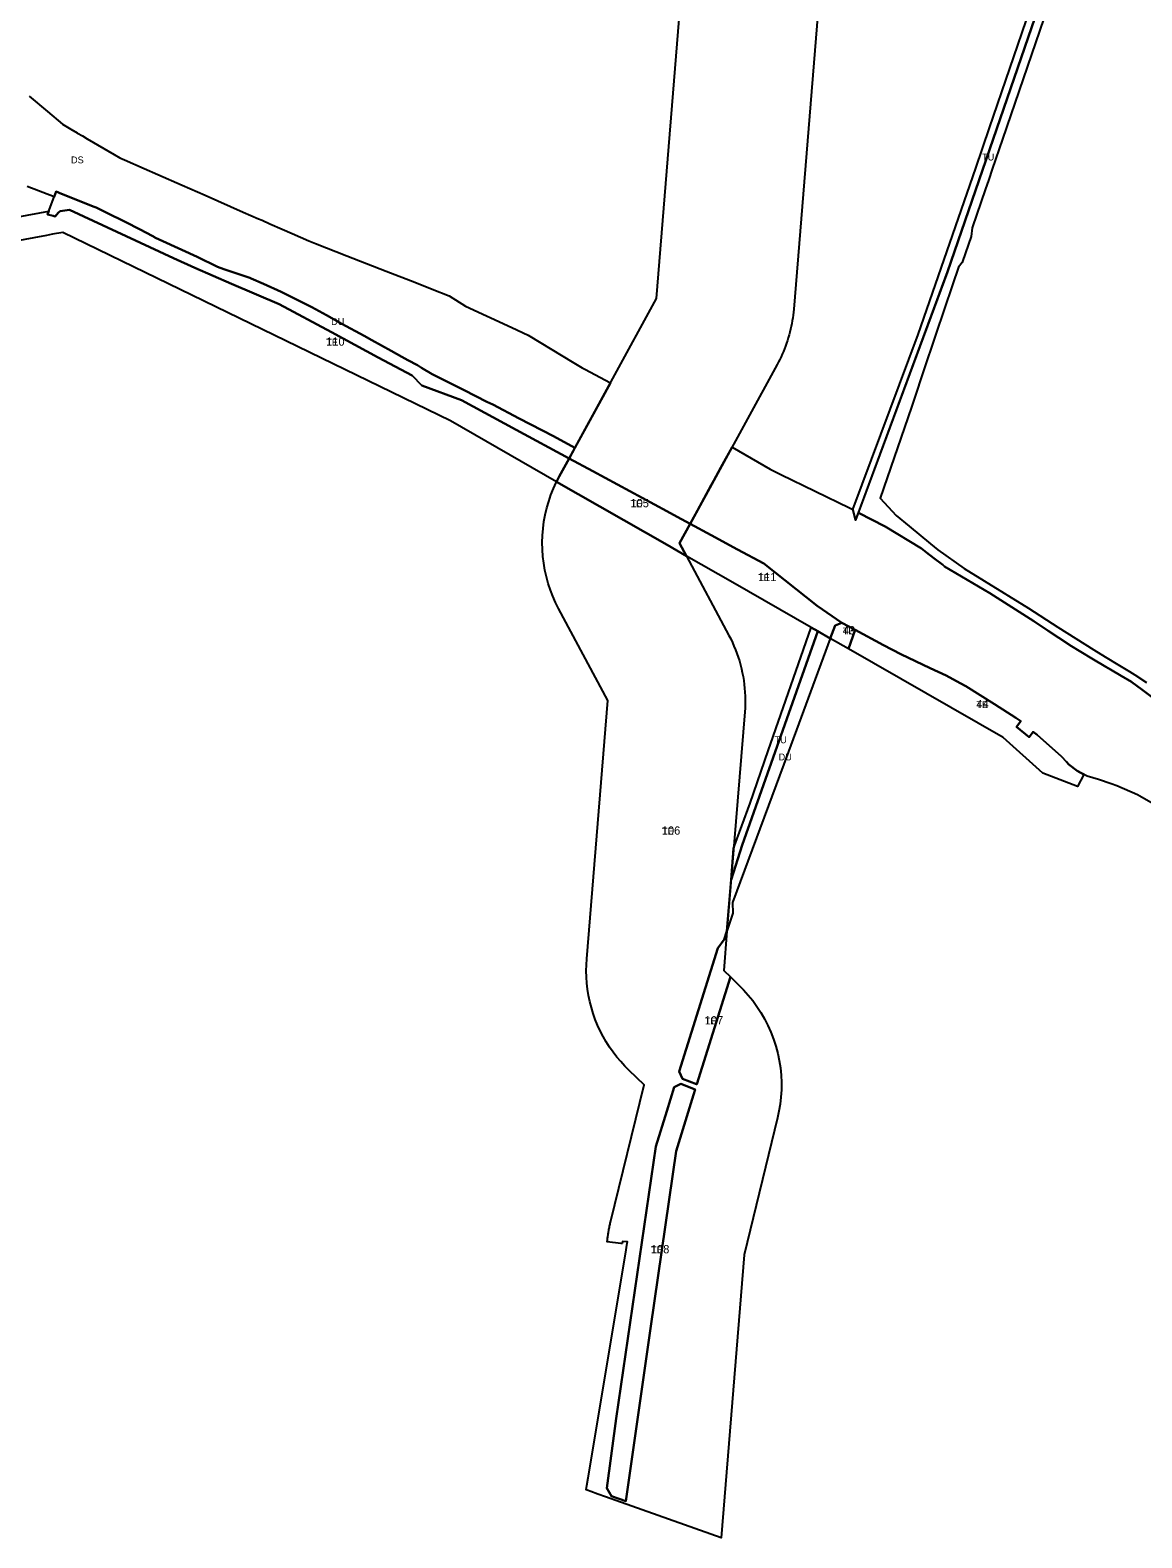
# Model space of a CAD drawing. Extents: x -545758 to -541641, y -1153152 to -1149975.
# Drawn here: x -545298 to -544489, y -1153152 to -1152056 of the extents above; entities that cross this region are included whole.
import ezdxf

# ---------------------------------------------------------------- set-up
doc = ezdxf.new("R2010")
doc.units = 0
for name, color, linetype in [('90310013', 7, 'Continuous'), ('90320013', 7, 'Continuous'), ('90380013', 7, 'Continuous'), ('90400023', 7, 'Continuous'), ('ID_navrh', 7, 'Continuous')]:
    doc.layers.add(name, color=color, linetype=linetype)

msp = doc.modelspace()

# ---------------------------------------------------------------- linework, layer by layer
at = {"layer": '90310013'}
for points in [[(-544481.23, -1152541), (-544489.11, -1152535.08), (-544496.36, -1152529.63), (-544496.46, -1152529.57), (-544504.15, -1152525.05), (-544511.83, -1152520.54), (-544515.2, -1152518.56), (-544525.39, -1152512.41), (-544541.43, -1152502.75), (-544541.58, -1152502.66), (-544557.13, -1152492.31), (-544567.56, -1152485.36), (-544599.6, -1152464.94), (-544632.56, -1152445.54), (-544633.87, -1152444.53), (-544640.28, -1152439.57), (-544645.63, -1152435.46), (-544649.29, -1152432.65), (-544675.73, -1152416.43), (-544695.241, -1152406.541), (-544630.44, -1152231.35), (-544571.74, -1152060.98), (-544513.04, -1151890.62)], [(-544560.42, -1152047.27), (-544590.33, -1152134.84), (-544597.88, -1152156.75), (-544600.43, -1152164.15), (-544603.03, -1152171.72), (-544606, -1152180.35), (-544612.56, -1152199.38), (-544613.15, -1152205.7), (-544617.23, -1152217.55), (-544619.66, -1152224.61), (-544622.37, -1152227.91), (-544626.78, -1152240.84), (-544638.99, -1152276.62), (-544641.43, -1152283.98), (-544645.92, -1152297.5), (-544656.61, -1152329.75), (-544679.3, -1152395.86), (-544667.8, -1152408.57), (-544658.35, -1152416.34), (-544642.8, -1152429.13), (-544637.45, -1152433.53), (-544618.29, -1152447.13), (-544603.68, -1152456.06), (-544571.54, -1152475.88), (-544550.16, -1152489.69), (-544523.97, -1152506.3), (-544515.72, -1152511.34), (-544506.5, -1152516.81), (-544498.11, -1152522), (-544494.22, -1152524.49), (-544485.69, -1152529.96)]]:
    msp.add_lwpolyline(points, dxfattribs=at)
for points in [[(-544901.361, -1152359.376), (-544905.561, -1152367.062), (-544944.14, -1152346.23), (-544983.88, -1152324.78), (-545012.67, -1152314.02), (-545019.73, -1152306.85), (-545044.41, -1152293.58), (-545078.51, -1152275.23), (-545116.45, -1152254.83), (-545151.09, -1152240.06), (-545177.97, -1152228.5), (-545193.36, -1152221.36), (-545269.04, -1152186.2), (-545275.73, -1152187.34), (-545277.02, -1152188.25), (-545278.59, -1152189.93), (-545279.36, -1152191.17), (-545281, -1152190.74), (-545284.96, -1152189.71), (-545280.21, -1152176.92), (-545278.79, -1152173), (-545274.74, -1152174.61), (-545251, -1152184.04), (-545249.66, -1152184.69), (-545241.98, -1152188.44), (-545228.61, -1152194.99), (-545227.97, -1152195.32), (-545218.21, -1152200.42), (-545208.46, -1152205.51), (-545206.49, -1152206.54), (-545201.09, -1152209.03), (-545176.24, -1152220.48), (-545161.43, -1152227.73), (-545156.68, -1152229.35), (-545145.25, -1152233.25), (-545137.75, -1152235.82), (-545136.81, -1152236.24), (-545127.98, -1152240.19), (-545115.02, -1152246), (-545092.74, -1152257.13), (-545082.1, -1152262.99), (-545070.9, -1152269.17), (-545054.69, -1152277.97), (-545049, -1152281.07), (-545035.06, -1152288.88), (-545027.26, -1152293.25), (-545023.01, -1152295.52), (-545015.99, -1152299.27), (-545012.93, -1152301.13), (-545005.28, -1152305.8), (-544982.08, -1152317.42), (-544965.36, -1152325.79), (-544961.14, -1152327.91), (-544941.85, -1152337.92), (-544916.99, -1152350.83)], [(-544790.854, -1152710.719), (-544787.811, -1152673.363), (-544779.71, -1152648.34), (-544724.668, -1152492.775), (-544715.712, -1152497.902), (-544749.46, -1152589.25), (-544786.7, -1152690.05), (-544786.64, -1152697.75)]]:
    msp.add_lwpolyline(points, close=True, dxfattribs=at)
at = {"layer": '90320013'}
for points in [[(-545298.3, -1152103.62), (-545285.05, -1152114.86), (-545274.15, -1152124.11), (-545267.99, -1152127.69), (-545263.39, -1152130.37), (-545263.11, -1152130.53), (-545259.63, -1152132.56), (-545259.58, -1152132.59), (-545256.06, -1152134.64), (-545236.53, -1152146.01), (-545232.45, -1152148.39), (-545229.05, -1152149.89), (-545228.91, -1152149.95), (-545214.72, -1152156.19), (-545204.71, -1152160.59), (-545196.9, -1152164.02), (-545194.72, -1152164.98), (-545187.16, -1152168.31), (-545170.34, -1152175.71), (-545142.62, -1152187.9), (-545131.55, -1152192.77), (-545128.96, -1152193.9), (-545123.33, -1152196.38), (-545114.46, -1152200.28), (-545107.13, -1152203.5), (-545094.87, -1152208.89), (-545089.98, -1152210.8), (-545067.38, -1152219.63), (-545038.6, -1152230.87), (-545017.89, -1152238.96), (-545005.27, -1152243.89), (-544992.95, -1152248.71), (-544981.08, -1152256.44), (-544947.32, -1152271.94), (-544935.3, -1152277.46), (-544902.29, -1152297.51), (-544896.18, -1152301.23), (-544894.29, -1152302.21), (-544875.471, -1152311.992), (-544901.361, -1152359.376), (-544916.99, -1152350.83), (-544941.85, -1152337.92), (-544961.14, -1152327.91), (-544965.36, -1152325.79), (-544982.08, -1152317.42), (-545005.28, -1152305.8), (-545012.93, -1152301.13), (-545015.99, -1152299.27), (-545023.01, -1152295.52), (-545027.26, -1152293.25), (-545035.06, -1152288.88), (-545049, -1152281.07), (-545054.69, -1152277.97), (-545070.9, -1152269.17), (-545082.1, -1152262.99), (-545092.74, -1152257.13), (-545115.02, -1152246), (-545127.98, -1152240.19), (-545136.81, -1152236.24), (-545137.75, -1152235.82), (-545145.25, -1152233.25), (-545156.68, -1152229.35), (-545161.43, -1152227.73), (-545176.24, -1152220.48), (-545201.09, -1152209.03), (-545206.49, -1152206.54), (-545208.46, -1152205.51), (-545218.21, -1152200.42), (-545227.97, -1152195.32), (-545228.61, -1152194.99), (-545241.98, -1152188.44), (-545249.66, -1152184.69), (-545251, -1152184.04), (-545274.74, -1152174.61), (-545278.79, -1152173), (-545280.21, -1152176.92), (-545299.89, -1152169.25)], [(-544475.81, -1152621.01), (-544490.57, -1152612.64), (-544492.33, -1152611.64), (-544507.3, -1152605.14), (-544511.43, -1152603.7), (-544520.47, -1152600.54), (-544528.77, -1152598.15), (-544536.19, -1152594.18), (-544542.2, -1152589.58), (-544543.88, -1152587.78), (-544547.55, -1152583.86), (-544565.31, -1152568.13), (-544568.11, -1152565.86), (-544570.95, -1152569.65), (-544580.27, -1152562.1), (-544577.06, -1152558.13), (-544580.79, -1152555.56), (-544596.19, -1152545.83), (-544617.01, -1152532.67), (-544621.12, -1152530.46), (-544631.29, -1152525.01), (-544642.93, -1152519.54), (-544664.42, -1152509.45), (-544676.91, -1152502.94), (-544697.46, -1152491.78), (-544707.28, -1152486.57), (-544725.21, -1152474.29), (-544764.06, -1152443.46), (-544783.135, -1152433.165), (-544783.135, -1152433.165), (-544802.23, -1152422.86), (-544817.569, -1152414.576), (-544817.569, -1152414.576), (-544813.735, -1152407.56), (-544807.394, -1152395.955), (-544802.253, -1152386.546), (-544800.315, -1152383), (-544795.19, -1152373.62), (-544787.104, -1152358.82), (-544759.32, -1152374.84), (-544751.588, -1152378.627), (-544751.588, -1152378.627), (-544701.77, -1152403.03), (-544699.22, -1152404.28), (-544697.22, -1152411.89), (-544695.241, -1152406.541), (-544695.241, -1152406.541), (-544675.73, -1152416.43), (-544649.29, -1152432.65), (-544645.63, -1152435.46), (-544640.28, -1152439.57), (-544633.87, -1152444.53), (-544632.56, -1152445.54), (-544599.6, -1152464.94), (-544567.56, -1152485.36), (-544557.13, -1152492.31), (-544541.58, -1152502.66), (-544541.43, -1152502.75), (-544525.39, -1152512.41), (-544515.2, -1152518.56), (-544511.83, -1152520.54), (-544504.15, -1152525.05), (-544496.46, -1152529.57), (-544496.36, -1152529.63), (-544489.11, -1152535.08), (-544481.23, -1152541)]]:
    msp.add_lwpolyline(points, dxfattribs=at)
at = {"layer": '90380013'}
for points in [[(-544569.04, -1152036.59), (-544535.68, -1151936.25), (-544517.9, -1151888.93), (-544511.33, -1151881.16), (-544513.04, -1151890.62), (-544571.74, -1152060.98), (-544630.44, -1152231.35), (-544697.22, -1152411.89), (-544699.22, -1152404.28), (-544651.83, -1152276.93), (-544609.92, -1152155.93), (-544599.8, -1152126.71), (-544570.31, -1152040.39)], [(-544787.811, -1152673.363), (-544785.958, -1152650.605), (-544773.83, -1152617.6), (-544760.95, -1152579.73), (-544729.515, -1152490), (-544724.668, -1152492.775), (-544779.71, -1152648.34)]]:
    msp.add_lwpolyline(points, close=True, dxfattribs=at)
at = {"layer": '90400023'}
for points in [[(-544642.403, -1151028.226), (-544742.287, -1152258.607), (-544742.479, -1152260.697), (-544742.714, -1152262.787), (-544742.994, -1152264.875), (-544743.318, -1152266.96), (-544743.686, -1152269.041), (-544744.098, -1152271.115), (-544744.553, -1152273.183), (-544745.053, -1152275.241), (-544745.595, -1152277.29), (-544746.181, -1152279.327), (-544746.81, -1152281.352), (-544747.481, -1152283.362), (-544748.193, -1152285.357), (-544748.947, -1152287.335), (-544749.742, -1152289.295), (-544750.576, -1152291.236), (-544751.45, -1152293.156), (-544752.363, -1152295.055), (-544753.313, -1152296.931), (-544754.3, -1152298.784), (-544817.569, -1152414.576), (-544827.152, -1152409.401), (-544834.56, -1152405.4), (-544888.36, -1152376.35), (-544905.561, -1152367.062), (-544905.561, -1152367.062), (-544841.973, -1152250.685), (-544744.745, -1151053.026)], [(-545527.014, -1152232.14), (-545284.061, -1152187.289), (-545284.96, -1152189.71), (-545281, -1152190.74), (-545279.36, -1152191.17), (-545278.59, -1152189.93), (-545277.02, -1152188.25), (-545275.73, -1152187.34), (-545269.04, -1152186.2), (-545193.36, -1152221.36), (-545177.97, -1152228.5), (-545151.09, -1152240.06), (-545116.45, -1152254.83), (-545078.51, -1152275.23), (-545044.41, -1152293.58), (-545019.73, -1152306.85), (-545012.67, -1152314.02), (-544983.88, -1152324.78), (-544944.14, -1152346.23), (-544905.561, -1152367.062), (-544912.79, -1152380.293), (-544914.692, -1152383.981), (-544991.828, -1152339.819), (-545273.959, -1152202.711), (-545281.366, -1152204.078), (-545285.772, -1152204.892), (-545616.018, -1152265.858)]]:
    msp.add_lwpolyline(points, dxfattribs=at)
for points in [[(-544825.243, -1152428.621), (-544820.193, -1152438.084), (-544834.403, -1152429.949), (-544914.692, -1152383.981), (-544912.79, -1152380.293), (-544905.561, -1152367.062), (-544888.36, -1152376.35), (-544834.56, -1152405.4), (-544827.152, -1152409.401), (-544817.569, -1152414.576)], [(-544892.65, -1153113.74), (-544891.723, -1153108.167), (-544864.7, -1152945.73), (-544863.34, -1152937.57), (-544863.21, -1152936.8), (-544866.69, -1152936.45), (-544866.77, -1152936.91), (-544866.95, -1152937.97), (-544867.93, -1152937.85), (-544877.906, -1152936.645), (-544877.891, -1152936.485), (-544877.811, -1152935.687), (-544877.724, -1152934.89), (-544877.631, -1152934.094), (-544877.532, -1152933.297), (-544877.427, -1152932.502), (-544877.315, -1152931.708), (-544877.196, -1152930.914), (-544877.072, -1152930.122), (-544876.941, -1152929.33), (-544876.804, -1152928.539), (-544876.66, -1152927.75), (-544876.51, -1152926.962), (-544876.355, -1152926.175), (-544876.192, -1152925.39), (-544876.024, -1152924.606), (-544875.849, -1152923.823), (-544875.669, -1152923.042), (-544875.482, -1152922.263), (-544851.11, -1152822.432), (-544862.031, -1152811.99), (-544865.112, -1152808.913), (-544868.083, -1152805.677), (-544870.933, -1152802.287), (-544873.649, -1152798.75), (-544876.221, -1152795.075), (-544878.638, -1152791.269), (-544880.892, -1152787.343), (-544882.973, -1152783.307), (-544884.874, -1152779.173), (-544886.588, -1152774.953), (-544888.11, -1152770.66), (-544889.435, -1152766.307), (-544890.56, -1152761.908), (-544891.483, -1152757.476), (-544892.204, -1152753.025), (-544892.723, -1152748.569), (-544893.042, -1152744.122), (-544893.164, -1152739.695), (-544893.093, -1152735.302), (-544892.833, -1152730.955), (-544877.53, -1152543.052), (-544913.266, -1152476.078), (-544915.431, -1152471.775), (-544917.409, -1152467.325), (-544919.185, -1152462.739), (-544920.749, -1152458.031), (-544922.088, -1152453.216), (-544923.193, -1152448.31), (-544924.055, -1152443.329), (-544924.669, -1152438.292), (-544925.029, -1152433.218), (-544925.132, -1152428.125), (-544924.978, -1152423.034), (-544924.568, -1152417.963), (-544923.904, -1152412.933), (-544922.993, -1152407.961), (-544921.839, -1152403.066), (-544920.452, -1152398.264), (-544918.842, -1152393.572), (-544917.02, -1152389.004), (-544914.998, -1152384.574), (-544914.692, -1152383.981), (-544834.403, -1152429.949), (-544820.193, -1152438.084), (-544789.414, -1152495.769), (-544788.11, -1152498.299), (-544786.873, -1152500.874), (-544785.706, -1152503.492), (-544784.611, -1152506.15), (-544783.589, -1152508.844), (-544782.644, -1152511.572), (-544781.775, -1152514.331), (-544780.985, -1152517.117), (-544780.275, -1152519.927), (-544779.645, -1152522.757), (-544779.098, -1152525.604), (-544778.632, -1152528.465), (-544778.249, -1152531.335), (-544777.95, -1152534.212), (-544777.733, -1152537.091), (-544777.599, -1152539.969), (-544777.547, -1152542.843), (-544777.577, -1152545.709), (-544777.688, -1152548.564), (-544777.879, -1152551.404), (-544790.854, -1152710.719), (-544792.82, -1152716.77), (-544797.52, -1152723.13), (-544825.61, -1152812.84), (-544823.15, -1152818.06), (-544812.87, -1152822), (-544812.66, -1152822.07), (-544788.338, -1152744.096), (-544782.332, -1152749.839), (-544778.755, -1152753.436), (-544775.324, -1152757.255), (-544772.057, -1152761.29), (-544768.973, -1152765.529), (-544766.09, -1152769.96), (-544763.426, -1152774.569), (-544760.996, -1152779.339), (-544758.814, -1152784.253), (-544756.892, -1152789.291), (-544755.239, -1152794.432), (-544753.865, -1152799.654), (-544752.773, -1152804.935), (-544751.968, -1152810.251), (-544751.448, -1152815.579), (-544751.213, -1152820.898), (-544751.258, -1152826.184), (-544751.576, -1152831.416), (-544752.158, -1152836.575), (-544752.994, -1152841.641), (-544754.073, -1152846.597), (-544778.35, -1152946.041), (-544794.921, -1153151.915), (-544879.05, -1153122.06), (-544884.74, -1153120.04), (-544889.85, -1153118.23), (-544892.452, -1153117.222), (-544893.18, -1153116.94)], [(-544820.193, -1152438.084), (-544825.243, -1152428.621), (-544817.569, -1152414.576), (-544802.23, -1152422.86), (-544783.135, -1152433.165), (-544764.06, -1152443.46), (-544725.21, -1152474.29), (-544707.28, -1152486.57), (-544712.22, -1152488.45), (-544715.712, -1152497.902), (-544724.668, -1152492.775), (-544729.515, -1152490), (-544786.656, -1152457.285)], [(-544702.513, -1152505.459), (-544715.712, -1152497.902), (-544712.22, -1152488.45), (-544707.28, -1152486.57), (-544697.46, -1152491.78)], [(-544561.127, -1152595.796), (-544590.019, -1152569.865), (-544702.513, -1152505.459), (-544697.46, -1152491.78), (-544676.91, -1152502.94), (-544664.42, -1152509.45), (-544642.93, -1152519.54), (-544631.29, -1152525.01), (-544621.12, -1152530.46), (-544617.01, -1152532.67), (-544596.19, -1152545.83), (-544580.79, -1152555.56), (-544577.06, -1152558.13), (-544580.27, -1152562.1), (-544570.95, -1152569.65), (-544568.11, -1152565.86), (-544565.31, -1152568.13), (-544547.55, -1152583.86), (-544543.88, -1152587.78), (-544542.2, -1152589.58), (-544536.19, -1152594.18), (-544531.193, -1152596.854), (-544535.811, -1152605.485)], [(-544792.82, -1152716.77), (-544790.854, -1152710.719), (-544793.194, -1152739.453), (-544788.338, -1152744.096), (-544812.66, -1152822.07), (-544812.87, -1152822), (-544823.15, -1152818.06), (-544825.61, -1152812.84), (-544797.52, -1152723.13)], [(-544864.36, -1153125.27), (-544848.299, -1153013.299), (-544846.11, -1152998.04), (-544827.86, -1152870.81), (-544815.05, -1152829.72), (-544814, -1152825.85), (-544824.27, -1152821.91), (-544829.15, -1152824.31), (-544834.52, -1152841.632), (-544842.53, -1152867.47), (-544871.48, -1153065.1), (-544878.23, -1153115.89), (-544874.79, -1153121.54)], [(-544848.299, -1153013.299), (-544864.36, -1153125.27), (-544874.79, -1153121.54), (-544878.23, -1153115.89), (-544871.48, -1153065.1), (-544842.53, -1152867.47), (-544834.52, -1152841.632), (-544829.15, -1152824.31), (-544824.27, -1152821.91), (-544814, -1152825.85), (-544815.05, -1152829.72), (-544827.86, -1152870.81), (-544846.11, -1152998.04)]]:
    msp.add_lwpolyline(points, close=True, dxfattribs=at)

# ---------------------------------------------------------------- texts
at = {"layer": '90310013'}
for rotation, p in [(0, (-545078.747, -1152270.031)), (360, (-544753.283, -1152586.624))]:
    msp.add_text('DU', height=5, rotation=rotation, dxfattribs=at).set_placement(p)
at = {"layer": '90320013'}
msp.add_text('DS', height=5, rotation=0, dxfattribs=at).set_placement((-545267.957, -1152152.507))
at = {"layer": '90380013'}
for rotation, p in [(0, (-544605.275, -1152150.415)), (360, (-544756.24, -1152574.145))]:
    msp.add_text('TU', height=5, rotation=rotation, dxfattribs=at).set_placement(p)
at = {"layer": '90400023'}
for rotation, p in [(360, (-545082.315, -1152285.09)), (0, (-544861.007, -1152402.573)), (0, (-544768.22, -1152456.239)), (360, (-544706.586, -1152495.033)), (360, (-544609.429, -1152548.632)), (0, (-544838.173, -1152640.602)), (0, (-544806.974, -1152778.582)), (360, (-544846.115, -1152945.009))]:
    msp.add_text('TE', height=5, rotation=rotation, dxfattribs=at).set_placement(p)
at = {"layer": 'ID_navrh'}
for s, rotation, p in [('110', 0, (-545082.315, -1152285.09)), ('105', 360, (-544861.007, -1152402.573)), ('111', 0, (-544768.22, -1152456.239)), ('43', 360, (-544706.586, -1152495.033)), ('44', 360, (-544609.429, -1152548.632)), ('106', 0, (-544838.173, -1152640.602)), ('107', 0, (-544806.974, -1152778.582)), ('108', 360, (-544846.115, -1152945.009))]:
    msp.add_text(s, height=6, rotation=rotation, dxfattribs=at).set_placement(p)

doc.saveas('drawing.dxf')
